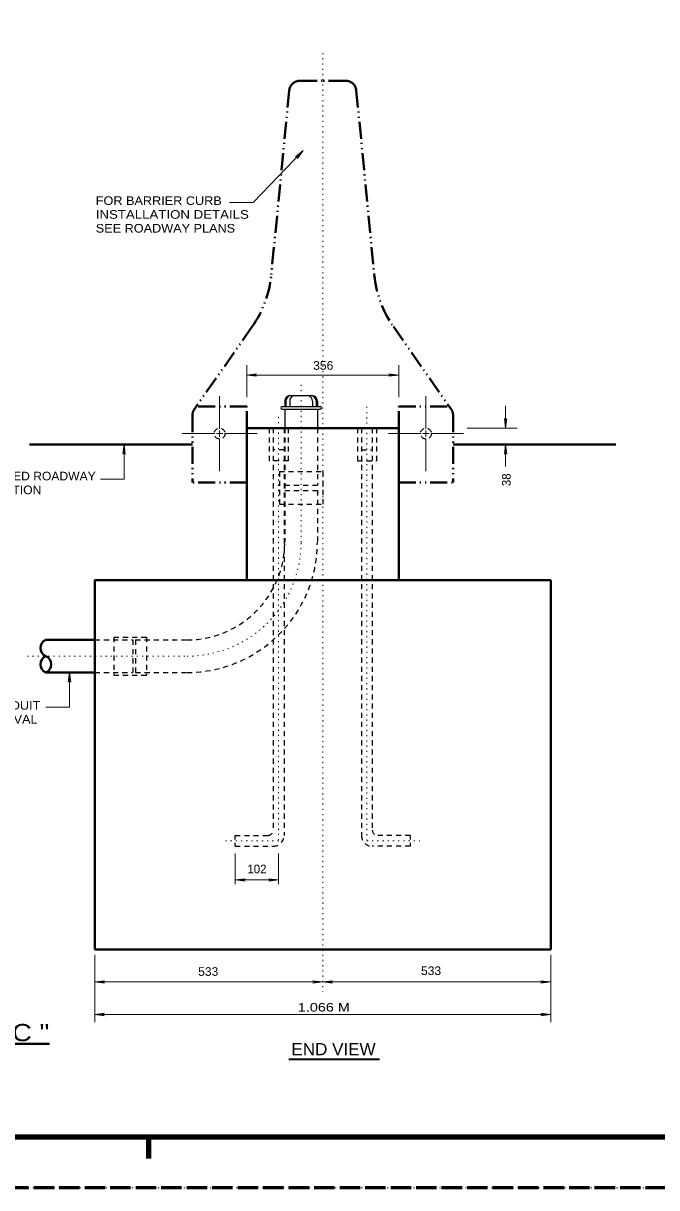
# Model space of a CAD drawing. Extents: x 312583 to 312854, y 144419 to 144597.
# Drawn here: x 312716.3 to 312772.2, y 144418.6 to 144521.4 of the extents above; entities that cross this region are included whole.
import ezdxf
from ezdxf.enums import TextEntityAlignment as Align

# ---------------------------------------------------------------- set-up
doc = ezdxf.new("R2010")
doc.units = 0
doc.header["$LTSCALE"] = 0.3
for name, pattern in [('DASH_DOUBLE_DOT', [9.2, 5, -1.2, 0.3, -1.2, 0.3, -1.2]), ('DOTTED', [1.5, 0.3, -1.2]), ('LONG_DASHED', [7.5, 6, -1.5]), ('SHORT_DASHED', [2.7, 1.5, -1.2])]:
    doc.linetypes.add(name, pattern=pattern)
for name, color, linetype, lineweight in [('1', 7, 'Continuous', 25), ('2', 7, 'Continuous', 13), ('62', 7, 'DOTTED', 13), ('63', 7, 'LONG_DASHED', 60)]:
    doc.layers.add(name, color=color, linetype=linetype, lineweight=lineweight)

msp = doc.modelspace()

# ---------------------------------------------------------------- linework, layer by layer
at = {"layer": '1', "linetype": 'DOTTED', "lineweight": 13}
for p, q in [((312742.7072, 144518.7222), (312742.7072, 144435.8992)), ((312746.6019, 144487.5035), (312746.6019, 144449.2009)), ((312738.8125, 144486.6142), (312738.8125, 144449.2009)), ((312716.6405, 144465.4925), (312730.7319, 144465.4925)), ((312738.8125, 144449.2009), (312734.1282, 144449.2009)), ((312746.6019, 144449.2009), (312751.2862, 144449.2009))]:
    msp.add_line(p, q, dxfattribs=at)
at = {"layer": '1', "linetype": 'DASH_DOUBLE_DOT', "lineweight": 40}
for p, q in [((312740.7062, 144516.2842), (312742.7072, 144516.2842)), ((312744.7159, 144516.2842), (312742.7072, 144516.2842)), ((312739.7479, 144515.4179), (312738.1609, 144499.1415)), ((312745.6665, 144515.4179), (312747.2535, 144499.1415)), ((312736.4742, 144494.5799), (312731.3835, 144487.3042)), ((312748.9402, 144494.5799), (312754.0385, 144487.3042)), ((312731.2072, 144486.7522), (312731.2072, 144480.8259)), ((312754.2072, 144486.7522), (312754.2072, 144480.8259)), ((312735.9989, 144480.8259), (312731.2072, 144480.8259)), ((312749.4155, 144480.8259), (312754.2072, 144480.8259))]:
    msp.add_line(p, q, dxfattribs=at)
at = {"layer": '1'}
for p, q in [((312739.8322, 144488.4925), (312741.7489, 144488.4925)), ((312739.1115, 144487.5342), (312742.4695, 144487.5342)), ((312739.3569, 144488.0172), (312739.3569, 144487.5342)), ((312739.4489, 144488.0172), (312739.4489, 144487.5342)), ((312739.7862, 144488.0172), (312739.7862, 144487.5342)), ((312741.7949, 144488.0172), (312741.7949, 144487.5342)), ((312742.1322, 144488.0172), (312742.1322, 144487.5342)), ((312742.2319, 144488.0172), (312742.2319, 144487.5342)), ((312739.1115, 144487.2965), (312742.4695, 144487.2965)), ((312739.3569, 144487.2965), (312739.3569, 144485.6175)), ((312742.2319, 144487.2965), (312742.2319, 144485.6175)), ((312734.9792, 144449.3159), (312734.9792, 144449.6839)), ((312750.4352, 144449.3159), (312750.4352, 144449.6839)), ((312734.9792, 144448.7255), (312734.9792, 144449.0169)), ((312750.4352, 144448.7255), (312750.4352, 144449.0169))]:
    msp.add_line(p, q, dxfattribs=at)
at = {"layer": '1', "lineweight": 40}
for p, q in [((312735.9989, 144485.6175), (312749.4155, 144485.6175)), ((312735.9989, 144472.2009), (312735.9989, 144485.6175)), ((312749.4155, 144472.2009), (312749.4155, 144485.6175)), ((312716.8322, 144484.1839), (312731.2072, 144484.1839)), ((312754.2072, 144484.1839), (312768.5822, 144484.1839)), ((312762.8322, 144439.6175), (312762.8322, 144472.2009)), ((312718.2735, 144466.9339), (312722.5822, 144466.9339)), ((312718.2735, 144464.0589), (312722.5822, 144464.0589)), ((312722.5822, 144439.6175), (312762.8322, 144439.6175))]:
    msp.add_line(p, q, dxfattribs=at)
at = {"layer": '1', "linetype": 'SHORT_DASHED'}
for p, q in [((312737.9769, 144485.6175), (312737.9769, 144482.7425)), ((312738.3372, 144485.6175), (312738.3372, 144450.1592)), ((312739.2955, 144485.6175), (312739.2955, 144449.6839)), ((312739.3569, 144485.6175), (312739.3569, 144475.5589)), ((312739.6559, 144485.6175), (312739.6559, 144482.7425)), ((312742.2319, 144485.6175), (312742.2319, 144480.5882)), ((312745.7662, 144485.6175), (312745.7662, 144482.7425)), ((312746.1189, 144485.6175), (312746.1189, 144449.6839)), ((312747.0772, 144485.6175), (312747.0772, 144450.1592)), ((312747.4375, 144485.6175), (312747.4375, 144482.7425)), ((312739.2955, 144483.7009), (312738.3372, 144483.7009)), ((312746.1189, 144483.7009), (312747.0772, 144483.7009)), ((312739.6559, 144482.7425), (312737.9769, 144482.7425)), ((312745.7662, 144482.7425), (312747.4375, 144482.7425)), ((312738.8739, 144481.7842), (312742.7072, 144481.7842)), ((312738.8739, 144481.7842), (312738.8739, 144478.9092)), ((312742.7072, 144481.7842), (312742.7072, 144478.9092)), ((312739.3569, 144480.5882), (312742.2319, 144480.5882)), ((312739.3569, 144480.1129), (312742.2319, 144480.1129)), ((312742.2319, 144480.1129), (312742.2319, 144475.5589)), ((312738.8739, 144478.9092), (312742.7072, 144478.9092)), ((312722.5822, 144466.9339), (312725.9402, 144466.9339)), ((312724.2612, 144467.1715), (312724.2612, 144463.8212)), ((312724.2612, 144467.1715), (312727.1362, 144467.1715)), ((312725.9402, 144466.9339), (312725.9402, 144464.0589)), ((312726.1779, 144466.9339), (312730.7319, 144466.9339)), ((312726.1779, 144466.9339), (312726.1779, 144464.0589)), ((312727.1362, 144467.1715), (312727.1362, 144463.8212)), ((312722.5822, 144464.0589), (312725.9402, 144464.0589)), ((312724.2612, 144463.8212), (312727.1362, 144463.8212)), ((312726.1779, 144464.0589), (312730.7319, 144464.0589)), ((312734.9792, 144449.6839), (312737.8542, 144449.6839)), ((312750.4352, 144449.6839), (312747.5602, 144449.6839)), ((312734.9792, 144448.7255), (312738.3372, 144448.7255)), ((312750.4352, 144448.7255), (312747.0772, 144448.7255))]:
    msp.add_line(p, q, dxfattribs=at)
at = {"layer": '1', "lineweight": 158}
for p, q in [((312616.5, 144423.0846), (312849, 144423.0846)), ((312727.35, 144421.1646), (312727.35, 144423.0846))]:
    msp.add_line(p, q, dxfattribs=at)
at = {"layer": '1', "linetype": 'DASH_DOUBLE_DOT', "lineweight": 40}
for points in [[(312735.9989, 144485.6175), (312735.9989, 144487.5342), (312731.5445, 144487.5342)], [(312749.4155, 144485.6175), (312749.4155, 144487.5342), (312753.8699, 144487.5342)]]:
    msp.add_lwpolyline(points, dxfattribs=at)
at = {"layer": '1', "lineweight": 40}
msp.add_lwpolyline([(312722.5822, 144439.6175), (312722.5822, 144472.2009), (312762.8322, 144472.2009)], dxfattribs=at)
at = {"layer": '1', "linetype": 'SHORT_DASHED'}
for centre in [(312733.604, 144485.1403), (312751.8123, 144485.1403)]:
    msp.add_circle(centre, 0.4792, dxfattribs=at)
at = {"layer": '1', "linetype": 'DASH_DOUBLE_DOT', "lineweight": 40}
for centre, radius, start, end in [((312740.7025, 144515.3278), 0.9583, 90, 174.42803), ((312744.7138, 144515.3278), 0.9583, 5.57197, 90), ((312728.6227, 144500.0748), 9.5833, 325.00798, 354.4278), ((312756.7936, 144500.0748), 9.5833, 185.5722, 214.99202), ((312732.1665, 144486.7549), 0.9583, 145.00945, 180), ((312753.2498, 144486.7549), 0.9583, 0, 34.99055)]:
    msp.add_arc(centre, radius, start, end, dxfattribs=at)
at = {"layer": '1'}
for centre, radius, start, end in [((312739.8332, 144488.0153), 0.4792, 90, 180), ((312740.0287, 144487.9427), 0.5853, 109.51984, 172.88159), ((312740.3165, 144488.0025), 0.5295, 111.7239, 178.61917), ((312741.2664, 144488.0025), 0.5295, 1.38083, 68.2761), ((312741.7498, 144488.0153), 0.4792, 0, 90), ((312741.5542, 144487.9427), 0.5853, 7.11841, 70.48016), ((312739.1144, 144487.4163), 0.1198, 90, 270), ((312742.4686, 144487.4163), 0.1198, 270, 90)]:
    msp.add_arc(centre, radius, start, end, dxfattribs=at)
at = {"layer": '1', "linetype": 'SHORT_DASHED'}
for centre, radius, start, end in [((312730.729, 144475.5569), 11.5, 270, 0), ((312730.729, 144475.5569), 8.625, 270, 0), ((312737.8571, 144450.1611), 0.4792, 270, 0), ((312738.3362, 144449.6819), 0.9583, 270, 0), ((312747.0801, 144449.6819), 0.9583, 180, 270), ((312747.5592, 144450.1611), 0.4792, 180, 270)]:
    msp.add_arc(centre, radius, start, end, dxfattribs=at)
at = {"layer": '1', "linetype": 'DOTTED', "lineweight": 13}
msp.add_arc((312730.729, 144475.5569), 10.0625, 270, 0, dxfattribs=at)
at = {"layer": '1', "lineweight": 40}
for centre, start, end in [((312718.5701, 144466.2132), 112.61986, 247.38013), ((312718.5701, 144464.7757), 112.61986, 247.38013), ((312717.9712, 144464.7757), 292.61986, 67.38013)]:
    msp.add_arc(centre, 0.7786, start, end, dxfattribs=at)
at = {"layer": '2'}
for p, q in [((312740.9899, 144510.1125), (312740.3152, 144509.5682)), ((312740.9899, 144510.1125), (312740.4685, 144509.4149)), ((312740.3152, 144509.5682), (312740.5835, 144509.6909)), ((312740.4685, 144509.4149), (312740.5835, 144509.6909)), ((312735.9989, 144488.3545), (312735.9989, 144491.1682)), ((312749.4155, 144488.3545), (312749.4155, 144491.1682)), ((312735.9989, 144490.3019), (312736.8652, 144490.4092)), ((312735.9989, 144490.3019), (312749.4155, 144490.3019)), ((312735.9989, 144490.3019), (312736.8652, 144490.1945)), ((312736.8652, 144490.4092), (312736.5892, 144490.3019)), ((312736.8652, 144490.1945), (312736.5892, 144490.3019)), ((312748.5492, 144490.4092), (312748.8252, 144490.3019)), ((312749.4155, 144490.3019), (312748.5492, 144490.4092)), ((312748.5492, 144490.1945), (312748.8252, 144490.3019)), ((312749.4155, 144490.3019), (312748.5492, 144490.1945)), ((312733.6069, 144485.5715), (312733.6069, 144488.4465)), ((312751.8152, 144485.5715), (312751.8152, 144488.4465)), ((312758.8455, 144485.6175), (312758.8455, 144487.5775)), ((312758.7382, 144486.4839), (312758.8455, 144486.2079)), ((312758.8455, 144485.6175), (312758.7382, 144486.4839)), ((312758.9529, 144486.4839), (312758.8455, 144486.2079)), ((312758.8455, 144485.6175), (312758.9529, 144486.4839)), ((312733.6069, 144485.1422), (312733.6069, 144485.4259)), ((312751.8152, 144485.1422), (312751.8152, 144485.4259)), ((312755.4415, 144485.6175), (312759.8652, 144485.6175)), ((312733.1699, 144485.1422), (312730.2949, 144485.1422)), ((312733.6069, 144485.1422), (312733.3155, 144485.1422)), ((312733.6069, 144485.1422), (312733.8905, 144485.1422)), ((312733.6069, 144485.1422), (312733.6069, 144484.8509)), ((312733.6069, 144484.7129), (312733.6069, 144481.8379)), ((312734.0362, 144485.1422), (312736.9112, 144485.1422)), ((312751.3782, 144485.1422), (312748.5032, 144485.1422)), ((312751.8152, 144485.1422), (312751.5239, 144485.1422)), ((312751.8152, 144485.1422), (312752.0989, 144485.1422)), ((312751.8152, 144485.1422), (312751.8152, 144484.8509)), ((312751.8152, 144484.7129), (312751.8152, 144481.8379)), ((312752.2445, 144485.1422), (312755.1195, 144485.1422)), ((312725.1735, 144484.1839), (312725.0662, 144483.3175)), ((312725.0662, 144483.3175), (312725.1735, 144483.5935)), ((312725.1735, 144484.1839), (312725.2809, 144483.3175)), ((312725.2809, 144483.3175), (312725.1735, 144483.5935)), ((312758.8455, 144484.1839), (312758.7382, 144483.3175)), ((312758.7382, 144483.3175), (312758.8455, 144483.5935)), ((312758.8455, 144482.245), (312758.8455, 144484.1839)), ((312758.8455, 144484.1839), (312758.9529, 144483.3175)), ((312758.9529, 144483.3175), (312758.8455, 144483.5935)), ((312720.3512, 144464.0589), (312720.2439, 144463.1925)), ((312720.3512, 144464.0589), (312720.4585, 144463.1925)), ((312720.2439, 144463.1925), (312720.3512, 144463.4685)), ((312720.4585, 144463.1925), (312720.3512, 144463.4685)), ((312734.9792, 144448.0815), (312734.9792, 144445.3675)), ((312738.8125, 144448.0815), (312738.8125, 144445.3675)), ((312734.9792, 144445.7509), (312735.8455, 144445.8582)), ((312734.9792, 144445.7509), (312738.8125, 144445.7509)), ((312734.9792, 144445.7509), (312735.8455, 144445.6435)), ((312735.8455, 144445.8582), (312735.5695, 144445.7509)), ((312735.8455, 144445.6435), (312735.5695, 144445.7509)), ((312737.9462, 144445.8582), (312738.2222, 144445.7509)), ((312738.8125, 144445.7509), (312737.9462, 144445.8582)), ((312737.9462, 144445.6435), (312738.2222, 144445.7509)), ((312738.8125, 144445.7509), (312737.9462, 144445.6435)), ((312722.5822, 144433.1929), (312722.5822, 144439.1345)), ((312762.8322, 144433.1929), (312762.8322, 144439.1345)), ((312722.5822, 144436.7425), (312723.4485, 144436.8499)), ((312722.5822, 144436.7425), (312723.4485, 144436.6352)), ((312723.4485, 144436.8499), (312723.1725, 144436.7425)), ((312723.4485, 144436.6352), (312723.1725, 144436.7425)), ((312741.8409, 144436.8499), (312742.1169, 144436.7425)), ((312742.7072, 144436.7425), (312741.8409, 144436.8499)), ((312741.8409, 144436.6352), (312742.1169, 144436.7425)), ((312742.7072, 144436.7425), (312741.8409, 144436.6352)), ((312742.7072, 144436.7425), (312743.5735, 144436.8499)), ((312742.7072, 144436.7425), (312743.5735, 144436.6352)), ((312743.5735, 144436.8499), (312743.2975, 144436.7425)), ((312743.5735, 144436.6352), (312743.2975, 144436.7425)), ((312761.9659, 144436.8499), (312762.2419, 144436.7425)), ((312762.8322, 144436.7425), (312761.9659, 144436.8499)), ((312761.9659, 144436.6352), (312762.2419, 144436.7425)), ((312762.8322, 144436.7425), (312761.9659, 144436.6352)), ((312722.5822, 144433.8675), (312723.4485, 144433.9749)), ((312722.5822, 144433.8675), (312762.8322, 144433.8675)), ((312722.5822, 144433.8675), (312723.4485, 144433.7602)), ((312723.4485, 144433.9749), (312723.1725, 144433.8675)), ((312723.4485, 144433.7602), (312723.1725, 144433.8675)), ((312761.9659, 144433.9749), (312762.2419, 144433.8675)), ((312762.8322, 144433.8675), (312761.9659, 144433.9749)), ((312761.9659, 144433.7602), (312762.2419, 144433.8675)), ((312762.8322, 144433.8675), (312761.9659, 144433.7602))]:
    msp.add_line(p, q, dxfattribs=at)
at = {"layer": '2', "linetype": 'DOTTED'}
msp.add_line((312740.7905, 144475.5589), (312740.7905, 144489.4355), dxfattribs=at)
at = {"layer": '2', "lineweight": 40}
msp.add_line((312690.9173, 144431.2812), (312718.5923, 144431.2812), dxfattribs=at)
at = {"layer": '2', "lineweight": 35}
msp.add_line((312739.7265, 144429.9422), (312747.7137, 144429.9422), dxfattribs=at)
at = {"layer": '2'}
for points in [[(312734.4732, 144505.5432), (312736.5585, 144505.5432), (312740.9899, 144510.1125)], [(312723.0882, 144481.1325), (312725.1735, 144481.1325), (312725.1735, 144484.1839)], [(312718.2659, 144460.9999), (312720.3512, 144460.9999), (312720.3512, 144464.0589)], [(312722.5822, 144436.7425), (312742.7072, 144436.7425), (312762.8322, 144436.7425)]]:
    msp.add_lwpolyline(points, dxfattribs=at)
at = {"layer": '62'}
msp.add_lwpolyline([(312601.2, 144418.5846), (312853.5, 144418.5846), (312853.5, 144596.7846)], dxfattribs=at)
at = {"layer": '63'}
msp.add_line((312851.75, 144418.5846), (312583.526, 144418.5846), dxfattribs=at)

# ---------------------------------------------------------------- texts
at = {"layer": '2'}
for s, width, p in [('FOR BARRIER CURB', 1.1, (312722.6733, 144505.3223)), ('INSTALLATION DETAILS', 1.15, (312722.6733, 144504.1023)), ('SEE ROADWAY PLANS', 1.1, (312722.6733, 144502.8823)), ('356', 1.05, (312741.8593, 144490.7737)), ('FINISHED ROADWAY', 1.05, (312711.8773, 144481.0113)), ('ELEVATION', 1.05, (312711.8773, 144479.7913)), ('ELEVATION OF CONDUIT', 1.1, (312704.2414, 144460.7712)), ('SUBJECT TO APPROVAL', 1.1, (312704.2414, 144459.5512)), ('533', 1.05, (312751.3761, 144437.3547)), ('533', 1.05, (312731.7067, 144437.2845)), ('1.066 M', 1.25, (312740.5057, 144434.1288))]:
    msp.add_text(s, height=0.76, dxfattribs=dict(at, width=width)).set_placement(p)
msp.add_text('38', height=0.76, rotation=90, dxfattribs=at).set_placement((312759.2857, 144480.4978))
msp.add_text('102', height=0.76, dxfattribs=at).set_placement((312736.0502, 144446.3341))
for s, height, width, p in [('CONCRETE CLASS " C "', 1.52, 1.2, (312704.6331, 144431.5153)), ('END VIEW', 1.07, 1.05, (312743.6563, 144430.2761))]:
    msp.add_text(s, height=height, dxfattribs=dict(at, width=width)).set_placement(p, align=Align.CENTER)

doc.saveas('drawing.dxf')
